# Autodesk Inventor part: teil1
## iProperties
Created: 2005-10
Part Number: teil1
Document SubType Name: Modeling
Designer: Bernhard Fetzer
Author: Bernhard Fetzer
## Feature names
1. Extrusion1
2. Extrusion2
3. Sweeping1
4. Rundung1 [Fillet]
5. Runde Anordnung1 [Circular Pattern]
6. Rundung2 [Fillet]
7. Rundung3 [Fillet]
8. Bohrung1 [Hole]
